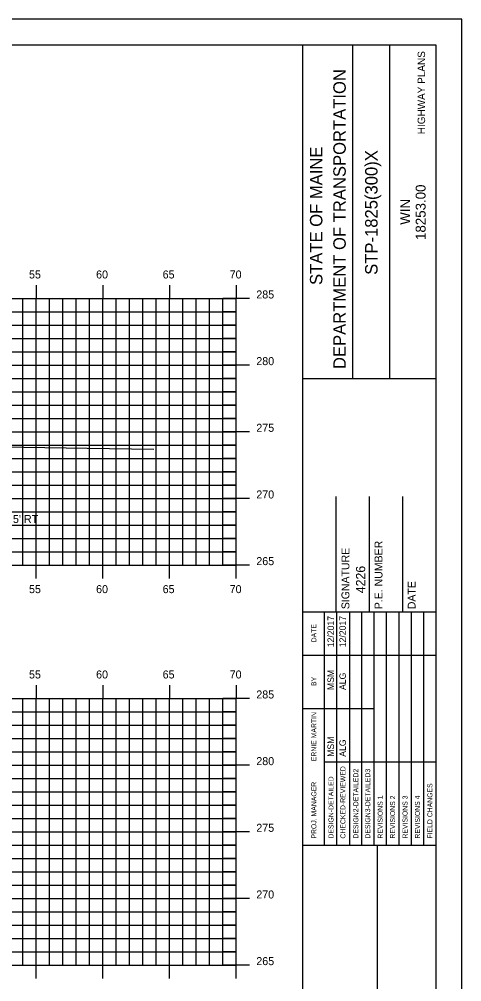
# Model space of a CAD drawing. Extents: x 854231 to 854401, y 366268 to 366378.
# Drawn here: x 854367.5 to 854400.7, y 366306 to 366378.2 of the extents above; entities that cross this region are included whole.
import ezdxf

# ---------------------------------------------------------------- set-up
doc = ezdxf.new("R2010")
doc.units = 0
for name, color, linetype in [('ANNOTATION', 7, 'Continuous'), ('BORDER', 7, 'Continuous'), ('D_Drainage_Text', 7, 'Continuous'), ('H_V ANNOTATION', 7, 'Continuous'), ('HIGHWAY_TITLE', 7, 'Continuous'), ('MAJOR', 7, 'Continuous'), ('MINOR', 7, 'Continuous'), ('PLOT BOUNDARY', 7, 'Continuous'), ('S_Roadway_Centerline', 7, 'Continuous')]:
    doc.layers.add(name, color=color, linetype=linetype)

msp = doc.modelspace()

# ---------------------------------------------------------------- linework, layer by layer
at = {"layer": 'BORDER'}
for p, q in [((854398.771, 366376.236), (854238.771, 366376.236)), ((854388.771, 366271.236), (854388.771, 366376.239)), ((854392.5, 366351.234), (854392.5, 366376.234)), ((854395.295, 366351.234), (854395.295, 366376.234)), ((854398.771, 366271.236), (854398.771, 366376.236)), ((854388.772, 366351.231), (854398.771, 366351.231)), ((854391.271, 366333.739), (854391.271, 366342.387)), ((854393.771, 366333.739), (854393.771, 366342.387)), ((854396.271, 366333.739), (854396.271, 366342.387)), ((854388.771, 366333.739), (854398.771, 366333.739)), ((854388.771, 366316.239), (854398.771, 366316.239)), ((854394.362, 366281.239), (854394.362, 366316.239))]:
    msp.add_line(p, q, dxfattribs=at)
for points in [[(854390.386, 366330.489), (854390.386, 366333.739)], [(854391.318, 366316.242), (854391.318, 366333.739)], [(854392.25, 366333.739), (854392.25, 366316.242)], [(854393.182, 366316.242), (854393.182, 366333.739)], [(854394.114, 366316.242), (854394.114, 366333.739)], [(854395.045, 366316.242), (854395.045, 366333.739)], [(854395.977, 366316.242), (854395.977, 366333.739)], [(854396.909, 366316.242), (854396.909, 366333.739)], [(854397.84, 366316.242), (854397.84, 366333.739)], [(854390.387, 366316.242), (854390.387, 366333.033)], [(854388.771, 366330.489), (854398.771, 366330.489)], [(854388.771, 366326.489), (854390.387, 366326.489)], [(854390.386, 366326.489), (854394.113, 366326.489)], [(854390.386, 366322.489), (854398.771, 366322.489)]]:
    msp.add_lwpolyline(points, dxfattribs=at)
at = {"layer": 'MAJOR'}
for p, q in [((854368.771, 366358.238), (854368.771, 366357.236)), ((854373.771, 366358.238), (854373.771, 366357.236)), ((854378.771, 366358.238), (854378.771, 366357.236)), ((854383.771, 366358.238), (854383.771, 366357.236)), ((854243.771, 366357.236), (854383.771, 366357.236)), ((854243.771, 366357.236), (854383.771, 366357.236)), ((854368.771, 366337.236), (854368.771, 366357.236)), ((854373.771, 366337.236), (854373.771, 366357.236)), ((854378.771, 366337.236), (854378.771, 366357.236)), ((854384.773, 366357.236), (854382.769, 366357.236)), ((854383.771, 366337.236), (854383.771, 366357.236)), ((854383.771, 366337.236), (854383.771, 366357.236)), ((854243.771, 366352.236), (854383.771, 366352.236)), ((854384.773, 366352.236), (854382.769, 366352.236)), ((854243.771, 366347.236), (854383.771, 366347.236)), ((854384.773, 366347.236), (854382.769, 366347.236)), ((854243.771, 366342.236), (854383.771, 366342.236)), ((854384.773, 366342.236), (854382.769, 366342.236)), ((854243.771, 366337.236), (854383.771, 366337.236)), ((854243.771, 366337.236), (854383.771, 366337.236)), ((854368.771, 366336.234), (854368.771, 366337.236)), ((854373.771, 366336.234), (854373.771, 366337.236)), ((854378.771, 366336.234), (854378.771, 366337.236)), ((854384.773, 366337.236), (854382.769, 366337.236)), ((854383.771, 366336.234), (854383.771, 366337.236)), ((854368.771, 366328.238), (854368.771, 366327.236)), ((854373.771, 366328.238), (854373.771, 366327.236)), ((854378.771, 366328.238), (854378.771, 366327.236)), ((854383.771, 366328.238), (854383.771, 366327.236)), ((854243.771, 366327.236), (854383.771, 366327.236)), ((854243.771, 366327.236), (854383.771, 366327.236)), ((854368.771, 366307.236), (854368.771, 366327.236)), ((854373.771, 366307.236), (854373.771, 366327.236)), ((854378.771, 366307.236), (854378.771, 366327.236)), ((854384.773, 366327.236), (854382.769, 366327.236)), ((854383.771, 366307.236), (854383.771, 366327.236)), ((854383.771, 366307.236), (854383.771, 366327.236)), ((854243.771, 366322.236), (854383.771, 366322.236)), ((854384.773, 366322.236), (854382.769, 366322.236)), ((854243.771, 366317.236), (854383.771, 366317.236)), ((854384.773, 366317.236), (854382.769, 366317.236)), ((854243.771, 366312.236), (854383.771, 366312.236)), ((854384.773, 366312.236), (854382.769, 366312.236)), ((854243.771, 366307.236), (854383.771, 366307.236)), ((854243.771, 366307.236), (854383.771, 366307.236)), ((854368.771, 366306.234), (854368.771, 366307.236)), ((854373.771, 366306.234), (854373.771, 366307.236)), ((854378.771, 366306.234), (854378.771, 366307.236)), ((854384.773, 366307.236), (854382.769, 366307.236)), ((854383.771, 366306.234), (854383.771, 366307.236))]:
    msp.add_line(p, q, dxfattribs=at)
at = {"layer": 'MINOR'}
for p, q in [((854367.771, 366337.236), (854367.771, 366357.236)), ((854369.771, 366337.236), (854369.771, 366357.236)), ((854370.771, 366337.236), (854370.771, 366357.236)), ((854371.771, 366337.236), (854371.771, 366357.236)), ((854372.771, 366337.236), (854372.771, 366357.236)), ((854374.771, 366337.236), (854374.771, 366357.236)), ((854375.771, 366337.236), (854375.771, 366357.236)), ((854376.771, 366337.236), (854376.771, 366357.236)), ((854377.771, 366337.236), (854377.771, 366357.236)), ((854379.771, 366337.236), (854379.771, 366357.236)), ((854380.771, 366337.236), (854380.771, 366357.236)), ((854381.771, 366337.236), (854381.771, 366357.236)), ((854382.771, 366337.236), (854382.771, 366357.236)), ((854243.771, 366356.236), (854383.771, 366356.236)), ((854383.771, 366356.236), (854382.769, 366356.236)), ((854243.771, 366355.236), (854383.771, 366355.236)), ((854383.771, 366355.236), (854382.769, 366355.236)), ((854243.771, 366354.236), (854383.771, 366354.236)), ((854383.771, 366354.236), (854382.769, 366354.236)), ((854243.771, 366353.236), (854383.771, 366353.236)), ((854383.771, 366353.236), (854382.769, 366353.236)), ((854243.771, 366351.236), (854383.771, 366351.236)), ((854383.771, 366351.236), (854382.769, 366351.236)), ((854243.771, 366350.236), (854383.771, 366350.236)), ((854383.771, 366350.236), (854382.769, 366350.236)), ((854243.771, 366349.236), (854383.771, 366349.236)), ((854383.771, 366349.236), (854382.769, 366349.236)), ((854243.771, 366348.236), (854383.771, 366348.236)), ((854383.771, 366348.236), (854382.769, 366348.236)), ((854243.771, 366346.236), (854383.771, 366346.236)), ((854383.771, 366346.236), (854382.769, 366346.236)), ((854243.771, 366345.236), (854383.771, 366345.236)), ((854383.771, 366345.236), (854382.769, 366345.236)), ((854243.771, 366344.236), (854383.771, 366344.236)), ((854383.771, 366344.236), (854382.769, 366344.236)), ((854243.771, 366343.236), (854383.771, 366343.236)), ((854383.771, 366343.236), (854382.769, 366343.236)), ((854243.771, 366341.236), (854383.771, 366341.236)), ((854383.771, 366341.236), (854382.769, 366341.236)), ((854243.771, 366340.236), (854383.771, 366340.236)), ((854383.771, 366340.236), (854382.769, 366340.236)), ((854243.771, 366339.236), (854383.771, 366339.236)), ((854383.771, 366339.236), (854382.769, 366339.236)), ((854243.771, 366338.236), (854383.771, 366338.236)), ((854383.771, 366338.236), (854382.769, 366338.236)), ((854367.771, 366307.236), (854367.771, 366327.236)), ((854369.771, 366307.236), (854369.771, 366327.236)), ((854370.771, 366307.236), (854370.771, 366327.236)), ((854371.771, 366307.236), (854371.771, 366327.236)), ((854372.771, 366307.236), (854372.771, 366327.236)), ((854374.771, 366307.236), (854374.771, 366327.236)), ((854375.771, 366307.236), (854375.771, 366327.236)), ((854376.771, 366307.236), (854376.771, 366327.236)), ((854377.771, 366307.236), (854377.771, 366327.236)), ((854379.771, 366307.236), (854379.771, 366327.236)), ((854380.771, 366307.236), (854380.771, 366327.236)), ((854381.771, 366307.236), (854381.771, 366327.236)), ((854382.771, 366307.236), (854382.771, 366327.236)), ((854243.771, 366326.236), (854383.771, 366326.236)), ((854383.771, 366326.236), (854382.769, 366326.236)), ((854243.771, 366325.236), (854383.771, 366325.236)), ((854383.771, 366325.236), (854382.769, 366325.236)), ((854243.771, 366324.236), (854383.771, 366324.236)), ((854383.771, 366324.236), (854382.769, 366324.236)), ((854243.771, 366323.236), (854383.771, 366323.236)), ((854383.771, 366323.236), (854382.769, 366323.236)), ((854243.771, 366321.236), (854383.771, 366321.236)), ((854383.771, 366321.236), (854382.769, 366321.236)), ((854243.771, 366320.236), (854383.771, 366320.236)), ((854383.771, 366320.236), (854382.769, 366320.236)), ((854243.771, 366319.236), (854383.771, 366319.236)), ((854383.771, 366319.236), (854382.769, 366319.236)), ((854243.771, 366318.236), (854383.771, 366318.236)), ((854383.771, 366318.236), (854382.769, 366318.236)), ((854243.771, 366316.236), (854383.771, 366316.236)), ((854383.771, 366316.236), (854382.769, 366316.236)), ((854243.771, 366315.236), (854383.771, 366315.236)), ((854383.771, 366315.236), (854382.769, 366315.236)), ((854243.771, 366314.236), (854383.771, 366314.236)), ((854383.771, 366314.236), (854382.769, 366314.236)), ((854243.771, 366313.236), (854383.771, 366313.236)), ((854383.771, 366313.236), (854382.769, 366313.236)), ((854243.771, 366311.236), (854383.771, 366311.236)), ((854383.771, 366311.236), (854382.769, 366311.236)), ((854243.771, 366310.236), (854383.771, 366310.236)), ((854383.771, 366310.236), (854382.769, 366310.236)), ((854243.771, 366309.236), (854383.771, 366309.236)), ((854383.771, 366309.236), (854382.769, 366309.236)), ((854243.771, 366308.236), (854383.771, 366308.236)), ((854383.771, 366308.236), (854382.769, 366308.236))]:
    msp.add_line(p, q, dxfattribs=at)
at = {"layer": 'PLOT BOUNDARY'}
msp.add_lwpolyline([(854230.678, 366268.177), (854400.678, 366268.177), (854400.678, 366378.177), (854230.678, 366378.177)], close=True, dxfattribs=at)
at = {"layer": 'S_Roadway_Centerline'}
msp.add_lwpolyline([(854363.052, 366346.167), (854372.586, 366346.011), (854377.58, 366345.942)], dxfattribs=at)

# ---------------------------------------------------------------- texts
at = {"layer": 'ANNOTATION'}
msp.add_text('4226', height=0.69, rotation=90, dxfattribs=at).set_placement((854393.436, 366335.13))
at = {"layer": 'BORDER'}
for s, height, p in [('DEPARTMENT OF TRANSPORTATION', 0.93176, (854391.978, 366351.942)), ('STATE OF MAINE', 0.93176, (854390.226, 366358.248)), ('STP-1825(300)X', 0.93176, (854394.363, 366359.008)), ('18253.00', 0.7453, (854397.967, 366361.623)), ('WIN', 0.7453, (854396.808, 366362.766)), ('P.E. NUMBER', 0.59055, (854394.732, 366333.932)), ('SIGNATURE', 0.5906, (854392.251, 366333.932)), ('DATE', 0.5906, (854397.212, 366333.932)), ('12/2017', 0.4845, (854391.094, 366331.081)), ('12/2017', 0.4845, (854391.988, 366331.081)), ('DATE', 0.3714, (854389.775, 366331.445)), ('MSM', 0.4845, (854391.094, 366327.872)), ('BY', 0.3714, (854389.775, 366328.174)), ('ALG', 0.4845, (854391.988, 366327.872)), ('ERNIE MARTIN', 0.37275, (854389.775, 366322.531)), ('MSM', 0.4845, (854391.094, 366322.863)), ('ALG', 0.4845, (854391.988, 366322.863)), ('CHECKED-REVIEWED', 0.37275, (854391.952, 366316.727)), ('DESIGN2-DETAILED2', 0.37275, (854392.921, 366316.727)), ('DESIGN3-DETAILED3', 0.37275, (854393.815, 366316.727)), ('PROJ. MANAGER', 0.37275, (854389.775, 366316.727)), ('DESIGN-DETAILED', 0.37275, (854391.058, 366316.727)), ('FIELD CHANGES', 0.37275, (854398.474, 366316.727)), ('REVISIONS 1', 0.37275, (854394.747, 366316.727)), ('REVISIONS 2', 0.37275, (854395.679, 366316.727)), ('REVISIONS 3', 0.37275, (854396.61, 366316.727)), ('REVISIONS 4', 0.37275, (854397.542, 366316.727))]:
    msp.add_text(s, height=height, rotation=90, dxfattribs=at).set_placement(p)
at = {"layer": 'D_Drainage_Text'}
msp.add_text("STA. 277+44.50, 19.8' RT TO STA. 277+48.00, 37.5' RT", height=0.6, dxfattribs=at).set_placement((854348.806, 366340.397))
at = {"layer": 'H_V ANNOTATION'}
for s, p in [('55', (854368.227, 366358.736)), ('60', (854373.257, 366358.736)), ('65', (854378.249, 366358.736)), ('70', (854383.273, 366358.736)), ('285', (854385.271, 366357.236)), ('280', (854385.271, 366352.236)), ('275', (854385.271, 366347.236)), ('270', (854385.271, 366342.236)), ('265', (854385.271, 366337.236)), ('55', (854368.227, 366335.136)), ('60', (854373.257, 366335.136)), ('65', (854378.249, 366335.136)), ('70', (854383.273, 366335.136)), ('55', (854368.227, 366328.736)), ('60', (854373.257, 366328.736)), ('65', (854378.249, 366328.736)), ('70', (854383.273, 366328.736)), ('285', (854385.271, 366327.236)), ('280', (854385.271, 366322.236)), ('275', (854385.271, 366317.236)), ('270', (854385.271, 366312.236)), ('265', (854385.271, 366307.236))]:
    msp.add_text(s, height=0.6, dxfattribs=at).set_placement(p)
at = {"layer": 'HIGHWAY_TITLE'}
msp.add_text('HIGHWAY PLANS', height=0.55901, rotation=90, dxfattribs=at).set_placement((854397.929, 366369.552))

doc.saveas('drawing.dxf')
